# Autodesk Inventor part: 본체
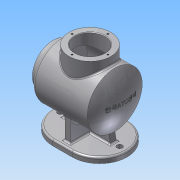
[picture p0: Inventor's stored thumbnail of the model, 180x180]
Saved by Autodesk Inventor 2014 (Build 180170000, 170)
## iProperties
Created: 2016-04
Part Number: 본체
Material: 알루미늄 6061
Document SubType Name: Modeling
Designer: 703-04
Density: 2.71 g/cm^3
Appearance: 알루미늄 - 평지
Mass: 912.076 g
Surface Area: 1262.17 cm^2
Volume: 336.559 cm^3
Author: 703-04
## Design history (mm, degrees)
sketch "스케치1"
  geometry: L1 (-17.5, 0)-(17.5, 0); L2 (-17.5, -50)-(17.5, -50); L3 (17.5, 50)-(-17.5, 50); A1 r 50 centre (-17.5, 0) between (-17.5, 50) and (-17.5, -50); A2 r 50 centre (17.5, 0) between (17.5, -50) and (17.5, 50); 1 further point
  constraints: 8 end point, 4 point on circle, 4 tangent, 2 centre point, 1 horizontal, 1 midpoint, 1 parallel
  dimensions: "d0" = 135 dimension on A2 A1; "d1" = 100 distance between parallel lines of L2 L3
extrude "돌출1" new body sketch "스케치1" distance "d2" = 10; taper "d3" = 0 deg
sketch "스케치2"
  geometry: L1 (17.5, 50)-(-17.5, 50) reference; L2 (0, 0)-(54, 0); L3 (0, 0)-(-54, 0); 2 further points
  constraints: 4 end point, 2 coincident, 1 collinear, 1 parallel
  dimensions: "d5" = 54 distance of L2.start L2.end; "d6" = 54 distance of L2.start L3.end
hole "구멍1" sketch "스케치2" at (54, 0), (-54, 0) diameter "d7" = 10; stored, may be unused: countersink angle "d11" = 90 deg, drill point angle "d13" = 118 deg; dims "d8" = 6, "d9" = 4, "d10" = 2, "d12" = 8
sketch "스케치3"
  geometry: L1 (5, -40)-(-5, -40); L2 (-5, -40)-(-5, 40); L3 (-5, 40)-(5, 40); L4 (5, 40)-(5, -40); L5 (5, -40)-(-5, 40); L6 (-5, -40)-(5, 40); L7 (-40, 5)-(40, 5); L8 (40, 5)-(40, -5); L9 (40, -5)-(-40, -5); L10 (-40, -5)-(-40, 5); L11 (-40, 5)-(40, -5); L12 (40, 5)-(-40, -5); 1 further point
  constraints: 24 end point, 4 midpoint, 4 parallel, 2 horizontal, 2 perpendicular
  dimensions: "d14" = 10 distance of L2.end L3.end; "d15" = 10 distance of L7.end L8.end; "d16" = 80 distance of L8.end L9.end; "d17" = 80 distance of L3.end L1.start
extrude "돌출2" join sketch "스케치3" distance "d18" = 69; taper "d19" = 0 deg
sketch "스케치4"
  geometry: L1 (5, 10)-(5, 79) reference; L2 (-5, 79)-(-40, 79) reference; L3 (-5, 10)-(5, 10) reference; L4 (-5, 10)-(-5, 79) reference; L5 (5, 79)-(-5, 79) reference; L6 (5, 10)-(5, 79) reference; L7 (0, 0)-(0, 79); C1 r 50 at (0, 79)
  constraints: 2 end point, 1 centre point, 1 coincident, 1 midpoint
  dimensions: "d21" = 100 diameter of C1
extrude "돌출3" join sketch "스케치4" stored distance "d22" = 110; taper "d23" = 0 deg
sketch "스케치5"
  geometry: C1 r 50 at (0, 0) reference; C2 r 38 at (0, 0); 1 further point
  constraints: 1 centre point, 1 coincident
  dimensions: "d24" = 76 diameter of C2
extrude "돌출4" join sketch "스케치5" distance "d25" = 12; taper "d26" = 0 deg
sketch "스케치6"
  geometry: C1 r 38 at (0, 0) reference; C2 r 27 at (0, 0); 1 further point
  constraints: 1 centre point, 1 coincident
  dimensions: "d27" = 54 diameter of C2
extrude "돌출5" cut sketch "스케치6" distance "d28" = 119; taper "d29" = 0 deg
node "작업 평면1"
sketch "스케치7"
  geometry: C1 r 38 at (0, 0); 2 further points
  constraints: 1 centre point, 1 coincident, 1 horizontal alignment
  dimensions: "d30" = 76 diameter of C1; "d60" = 5 distance of point (0, 0) point (-5, 0)
extrude "돌출6" join sketch "스케치7" stored distance "d31" = 50; taper "d32" = 0 deg
sketch "스케치8"
  geometry: L1 (0, 0)-(0, 144); L2 (17.5, 0)-(-17.5, 0) reference; L3 (0, 144)-(-63.14, 144); L4 (0, 144)-(69.924, 144); L5 (-63.14, 144)-(69.924, 144); L6 (69.924, 144)-(69.924, 164.557); L7 (69.924, 164.557)-(-63.14, 164.557); L8 (-63.14, 164.557)-(-63.14, 144)
  constraints: 14 end point, 3 parallel, 2 perpendicular, 1 collinear, 1 horizontal
  dimensions: "d33" = 144 distance of L1.start L1.end
extrude "돌출7" cut sketch "스케치8" stored distance "d34" = 100; taper "d35" = 0 deg
sketch "스케치9"
  geometry: L1 (67, 106)-(67, 52) reference; L2 (67, 79)-(-78.056, 79); L3 (67, 79)-(75.29, 79); L4 (52, 79)-(-51.783, 79); L5 (-51.783, 79)-(-51.783, 126); L6 (-51.783, 126)-(52, 126); L7 (52, 126)-(52, 79); 1 further point
  constraints: 12 end point, 2 parallel, 2 perpendicular, 1 collinear, 1 horizontal, 1 midpoint, 1 point on line
  dimensions: "d36" = 15 distance between parallel lines of L7 L1; "d37" = 94 diameter of L6 L2
revolve "회전1" sketch "스케치9" stored, may be unused: angle "d38" = 90 deg
sketch "스케치10"
  geometry: C1 r 38 at (0, 0) reference; C2 r 27 at (0, 0)
  constraints: 1 centre point, 1 coincident
  dimensions: "d39" = 54 diameter of C2
extrude "돌출8" cut sketch "스케치10" distance "d40" = 50; taper "d41" = 0 deg
sketch "스케치11"
  geometry: C1 r 38 at (0, 0) reference; A1 r 32.5 centre (0, 0) between (0, 32.5) and (32.5, 0); 2 further points
  constraints: 4 point on circle, 1 centre point, 1 coincident
  dimensions: "d42" = 65 diameter of A1
hole "구멍2" sketch "스케치11" at (0, 32.5), (32.5, 0), (-32.5, 0), (0, -32.5) diameter "d43" = 3.242; stored, may be unused: countersink angle "d47" = 82 deg, drill point angle "d49" = 118 deg; dims "d44" = 8, "d45" = 3.023, "d46" = 2, "d48" = 10
sketch "스케치12"
  geometry: C1 r 38 at (0, 0) reference; A1 r 32.5 centre (0, 0) between (32.5, 0) and (0, -32.5); 3 further points
  constraints: 4 point on circle, 1 centre point, 1 coincident
  dimensions: "d50" = 65 diameter of A1
hole "구멍3" sketch "스케치12" at (32.5, 0), (0, -32.5), (0, 32.5), (-32.5, 0) diameter "d51" = 3.242; stored, may be unused: countersink angle "d55" = 82 deg, drill point angle "d57" = 118 deg; dims "d52" = 8, "d53" = 3.023, "d54" = 2, "d56" = 10
sketch "스케치13"
  geometry: L1 (-52, 106)-(-52, 52) reference; L2 (67, 106)-(67, 52) reference; L3 (67, 41)-(67, 117) reference; L4 (55, 129)-(-55, 129) reference; L5 (-51.783, 126)-(52, 126) reference; L6 (65.33, 79)-(-89.468, 79); L7 (-27, 144)-(27, 144) reference; 1 further point
  constraints: 2 end point, 1 parallel
sketch "스케치14"
  geometry: L1 (0, 159.146)-(0, 28.979); L2 (65.33, 79)-(-89.468, 79) reference; L3 (-51.783, 52)-(-51.783, 106) reference; L4 (-51.783, 32)-(-51.783, 126) reference; L5 (-55, 129)-(-55, 29) reference; L6 (-45, 79)-(-45, 129); L7 (-45, 79)-(-55, 79); A1 r 130 centre (75, 79) between (-45, 129) and (-55, 79); 2 further points
  constraints: 6 end point, 2 point on circle, 2 point on line, 1 centre point, 1 parallel, 1 tangent, 1 vertical
  dimensions: "d62" = 10 distance from line of L5 L6.start
revolve "회전2" stored, may be unused: angle "d63" = 90 deg
sketch "스케치15"
  geometry: L1 (-45, 126)-(-45, 32) reference; L2 (-45, 79)-(-45, 148.156); L3 (55, 129)-(-55, 129) reference; L4 (-55, 129)-(-55, 29) reference; L5 (-45, 129)-(-57.514, 129); L6 (-57.514, 129)-(-57.514, 25.826); L7 (-57.514, 25.826)-(-45, 25.826); L8 (-45, 25.826)-(-45, 129); 1 further point
  constraints: 10 end point, 2 parallel, 2 point on line, 1 collinear, 1 horizontal, 1 midpoint, 1 perpendicular
extrude "돌출9" cut sketch "스케치15" stored distance "d64" = 100; taper "d65" = 0 deg
fillet "모깎기1" dims "d67" = 3
fillet "모깎기2" dims "d68" = 3
chamfer "모따기1" distance "d70" = 1; stored, may be unused: second distance "d71" = 2, angle "d72" = 45 deg
sketch "스케치17"
  geometry: L1 (-45, 29)-(-45, 129) reference; L2 (-59.813, 79)-(-56.813, 79); A1 r 115.996 centre (59.109, 74.85) between (-45, 126) and (-56.813, 79); A2 r 91.794 centre (31.981, 79) between (-45, 129) and (-59.813, 79); 1 further point
  constraints: 4 point on circle, 2 centre point, 2 end point, 1 point on line
  dimensions: "d73" = 3 distance of L2.start L2.end; "d74" = 3 distance of L1.end A1.start
revolve "회전4" sketch "스케치17" stored, may be unused: angle "d75" = 90 deg
sketch "스케치18"
  geometry: A1 r 91.794 centre (31.981, 79) between (-45, 129) and (-45, 29) reference; 1 further point
sketch "스케치19"
  geometry: L1 (43, 10)-(40.072, 26.607); L2 (5.023, 26.607)-(40.023, 26.607) reference; L3 (8, 10)-(43, 10) reference; L4 (40.072, 26.607)-(40.056, 26.697); L5 (40.056, 26.697)-(40.003, 26.994); L6 (40.003, 26.994)-(40.003, 10); 1 further point
  constraints: 8 end point, 2 collinear, 2 point on line, 1 perpendicular
  dimensions: "d77" = 100 deg angle of L1 L3
extrude "돌출10" join sketch "스케치19" stored distance "d78" = 10; taper "d79" = 0 deg
fillet "모깎기4" dims "d80" = 3
fillet "모깎기5" dims "d81" = 5
node "작업 평면2"
sketch "스케치21"
  geometry: L1 (-1.621, 144)-(1.621, 144) reference; 2 further points
  constraints: 1 other
feature "엠보싱1" sketch "스케치21" dims "d0" = 135, "d1" = 100, "d14" = 10, "d17" = 80, "d87" = 0.5, "d88" = 0
node "솔리드1"
mirror "대칭1"
node "투영된 루프1"
